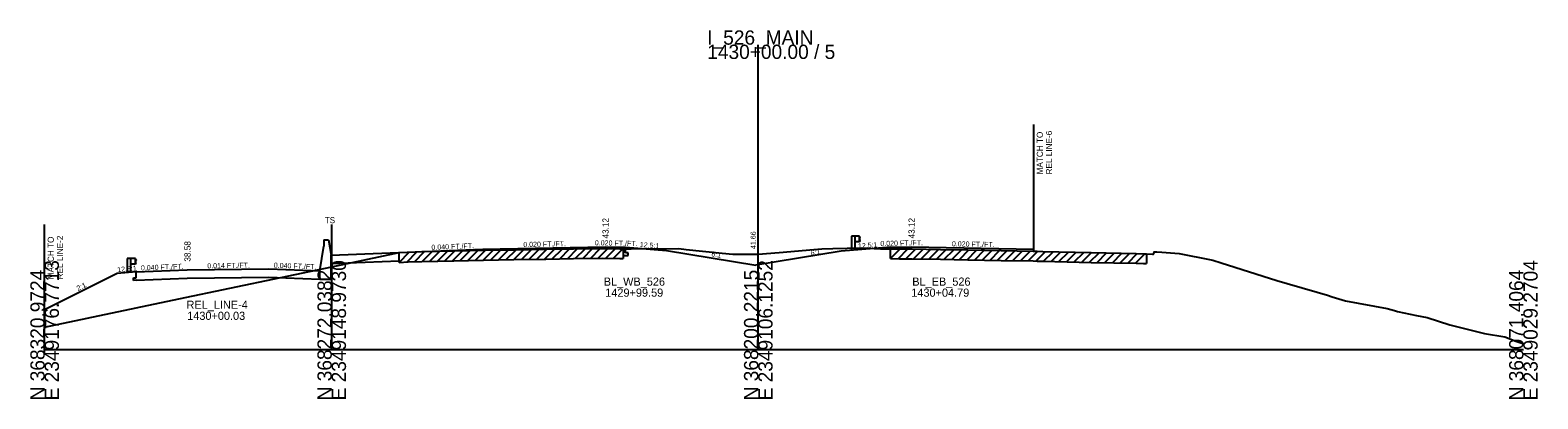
# Model space of a CAD drawing. Extents: x -170 to 2527928, y -10 to 1619750.
# Drawn here: x 3997.2 to 4292.7, y 7490.3 to 7562.6 of the extents above; entities that cross this region are included whole.
import ezdxf

# ---------------------------------------------------------------- set-up
doc = ezdxf.new("R2010")
doc.units = 0
for name, color, linetype in [('RD_GPK_XS_Cell', 7, 'Continuous'), ('RD_PD_NOISE-WALL-GM', 7, 'Continuous'), ('RD_XS_Base', 7, 'Continuous'), ('RD_XS_EarthShd', 7, 'Continuous'), ('RD_XS_ExGround', 7, 'Continuous'), ('RD_XS_ExPaveRet', 7, 'Continuous'), ('RD_XS_GR', 7, 'Continuous'), ('RD_XS_MatchLine', 7, 'Continuous'), ('RD_XS_Pave', 7, 'Continuous'), ('RD_XS_PaveShd', 7, 'Continuous'), ('RD_XS_TieSlope', 7, 'Continuous'), ('RD_XS_TX_Elev_EX', 7, 'Continuous'), ('RD_XS_TX_Slope', 7, 'Continuous'), ('RD_XS_TX_Station', 7, 'Continuous')]:
    doc.layers.add(name, color=color, linetype=linetype)

msp = doc.modelspace()

# ---------------------------------------------------------------- linework, layer by layer
at = {"layer": 'RD_GPK_XS_Cell'}
for p, q in [((4139.91, 7500), (4139.91, 7559.72)), ((4000, 7500), (4056.28, 7500)), ((4056.28, 7500), (4139.91, 7500)), ((4139.91, 7500), (4289.91, 7500))]:
    msp.add_line(p, q, dxfattribs=at)
at = {"layer": 'RD_PD_NOISE-WALL-GM'}
for p, q in [((4053.95, 7515.39), (4054.72, 7520.21)), ((4054.72, 7521.45), (4055.68, 7521.45)), ((4054.72, 7521.45), (4054.72, 7520.21)), ((4055.68, 7521.45), (4056.17, 7518.45)), ((4056.17, 7513.76), (4056.17, 7518.45)), ((4053.95, 7513.76), (4056.17, 7513.76))]:
    msp.add_line(p, q, dxfattribs=at)
at = {"layer": 'RD_XS_Base'}
for p, q in [((4113.91, 7518.91), (4113.91, 7520.04)), ((4165.91, 7519.69), (4165.91, 7520.04)), ((4056.17, 7516.82), (4069.49, 7517.35)), ((4113.41, 7518.42), (4113.91, 7518.41)), ((4114.41, 7518.9), (4113.91, 7518.91)), ((4113.91, 7518.41), (4114.41, 7518.4)), ((4114.41, 7518.4), (4114.41, 7518.9)), ((4193.91, 7519.25), (4193.91, 7519.64)), ((4017.45, 7514.02), (4017.95, 7514.04)), ((4017.45, 7513.52), (4017.45, 7514.02)), ((4017.95, 7514.04), (4017.95, 7515.18)), ((4017.95, 7513.54), (4027.95, 7513.94)), ((4027.95, 7513.94), (4043.95, 7514.16)), ((4043.95, 7514.16), (4053.95, 7513.76)), ((4053.95, 7513.76), (4053.95, 7515.39)), ((4017.95, 7513.54), (4017.45, 7513.52))]:
    msp.add_line(p, q, dxfattribs=at)
at = {"layer": 'RD_XS_EarthShd'}
for p, q in [((4113.91, 7520.04), (4121.91, 7519.4)), ((4165.91, 7520.04), (4156.16, 7519.26)), ((4017.95, 7515.18), (4014.2, 7514.88))]:
    msp.add_line(p, q, dxfattribs=at)
at = {"layer": 'RD_XS_ExGround'}
msp.add_lwpolyline([(4000, 7504.37), (4026.31, 7509.92), (4056.28, 7516.21), (4069.49, 7518.98), (4071.28, 7519.05), (4073.98, 7519.17), (4080.19, 7519.29), (4086.04, 7519.43), (4091.97, 7519.53), (4098.26, 7519.63), (4103.69, 7519.7), (4109.43, 7519.79), (4112.78, 7519.71), (4113.41, 7519.7), (4114.98, 7519.68), (4124.31, 7519.74), (4125.75, 7519.59), (4132.81, 7518.83), (4134.91, 7518.68), (4139.43, 7518.63), (4139.91, 7518.66), (4143.98, 7518.96), (4150.81, 7519.59), (4152.37, 7519.71), (4154.54, 7519.75), (4160.12, 7519.91), (4163.87, 7519.7), (4165.84, 7519.69), (4167.6, 7519.68), (4170.06, 7519.68), (4175.64, 7519.59), (4180.99, 7519.49), (4187.52, 7519.37), (4193.79, 7519.25), (4194.6, 7519.23), (4195.72, 7519.19), (4205.17, 7518.98), (4214.01, 7518.79), (4215.46, 7518.75), (4216.05, 7518.73), (4217.17, 7518.66), (4217.4, 7518.64), (4217.52, 7519.02), (4217.54, 7519.1), (4217.95, 7519.1), (4218.04, 7519.1), (4219.04, 7519.04), (4222.42, 7518.79), (4228.73, 7517.56), (4229.04, 7517.5), (4230.64, 7516.99), (4241.58, 7513.5), (4243.61, 7512.92), (4249.46, 7511.2), (4251.48, 7510.61), (4252.42, 7510.31), (4255.06, 7509.5), (4263.19, 7508), (4264.62, 7507.65), (4265.24, 7507.45), (4268.97, 7506.64), (4271.03, 7506.27), (4275.47, 7504.79), (4282.31, 7503.13), (4286.29, 7502.48), (4288.46, 7501.6), (4289.62, 7501.2), (4289.91, 7501.15)], dxfattribs=at)
at = {"layer": 'RD_XS_ExPaveRet'}
for p, q in [((4105.49, 7517.81), (4107.44, 7519.76)), ((4106.99, 7517.83), (4108.94, 7519.78)), ((4108.49, 7517.86), (4110.4, 7519.76)), ((4069.49, 7517.06), (4071.49, 7519.06)), ((4069.49, 7517.06), (4069.49, 7518.98)), ((4069.49, 7517.06), (4071.28, 7517.13)), ((4070.99, 7517.12), (4072.99, 7519.12)), ((4071.28, 7517.13), (4073.98, 7517.25)), ((4072.49, 7517.18), (4074.48, 7519.18)), ((4073.98, 7517.25), (4080.19, 7517.37)), ((4073.99, 7517.25), (4075.95, 7519.21)), ((4075.49, 7517.28), (4077.45, 7519.24)), ((4076.99, 7517.31), (4078.95, 7519.27)), ((4078.49, 7517.34), (4080.45, 7519.3)), ((4079.99, 7517.37), (4081.95, 7519.33)), ((4080.19, 7517.37), (4086.04, 7517.51)), ((4081.49, 7517.41), (4083.45, 7519.37)), ((4082.99, 7517.44), (4084.95, 7519.41)), ((4084.49, 7517.48), (4086.45, 7519.44)), ((4085.99, 7517.51), (4087.94, 7519.46)), ((4086.04, 7517.51), (4091.97, 7517.61)), ((4087.49, 7517.54), (4089.44, 7519.49)), ((4088.99, 7517.56), (4090.94, 7519.51)), ((4090.49, 7517.59), (4092.44, 7519.54)), ((4091.97, 7517.61), (4098.26, 7517.71)), ((4091.99, 7517.61), (4093.94, 7519.56)), ((4093.49, 7517.64), (4095.44, 7519.58)), ((4094.99, 7517.66), (4096.94, 7519.61)), ((4096.49, 7517.68), (4098.44, 7519.63)), ((4097.99, 7517.71), (4099.93, 7519.65)), ((4098.26, 7517.71), (4103.69, 7517.78)), ((4099.49, 7517.73), (4101.43, 7519.67)), ((4100.99, 7517.74), (4102.93, 7519.69)), ((4102.49, 7517.76), (4104.43, 7519.71)), ((4103.69, 7517.78), (4109.43, 7517.87)), ((4103.99, 7517.78), (4105.94, 7519.73)), ((4109.43, 7517.87), (4112.78, 7517.79)), ((4109.99, 7517.86), (4111.86, 7519.73)), ((4111.49, 7517.82), (4113.37, 7519.7)), ((4112.78, 7517.79), (4113.41, 7517.78)), ((4113.41, 7519.7), (4113.41, 7517.78)), ((4165.84, 7517.78), (4165.84, 7519.69)), ((4165.84, 7517.78), (4167.74, 7519.68)), ((4165.84, 7517.78), (4167.6, 7517.76)), ((4167.34, 7517.76), (4169.25, 7519.68)), ((4167.6, 7517.76), (4170.06, 7517.76)), ((4168.84, 7517.76), (4170.75, 7519.67)), ((4170.06, 7517.76), (4175.64, 7517.67)), ((4170.34, 7517.76), (4172.22, 7519.64)), ((4171.84, 7517.73), (4173.72, 7519.62)), ((4173.34, 7517.71), (4175.22, 7519.59)), ((4174.84, 7517.68), (4176.72, 7519.57)), ((4175.64, 7517.67), (4180.99, 7517.57)), ((4176.34, 7517.66), (4178.22, 7519.54)), ((4177.84, 7517.63), (4179.72, 7519.51)), ((4179.34, 7517.6), (4181.22, 7519.48)), ((4180.84, 7517.57), (4182.72, 7519.46)), ((4180.99, 7517.57), (4187.52, 7517.45)), ((4182.34, 7517.55), (4184.22, 7519.43)), ((4183.84, 7517.52), (4185.72, 7519.4)), ((4185.34, 7517.49), (4187.22, 7519.37)), ((4186.84, 7517.46), (4188.72, 7519.35)), ((4187.52, 7517.45), (4193.79, 7517.34)), ((4188.34, 7517.44), (4190.22, 7519.32)), ((4189.84, 7517.41), (4191.72, 7519.29)), ((4191.34, 7517.38), (4193.22, 7519.26)), ((4192.84, 7517.35), (4194.71, 7519.22)), ((4193.79, 7517.34), (4194.6, 7517.31)), ((4194.34, 7517.32), (4196.2, 7519.18)), ((4194.6, 7517.31), (4195.72, 7517.27)), ((4195.72, 7517.27), (4205.17, 7517.06)), ((4195.84, 7517.27), (4197.71, 7519.14)), ((4197.34, 7517.24), (4199.21, 7519.11)), ((4198.84, 7517.2), (4200.71, 7519.08)), ((4200.34, 7517.17), (4202.21, 7519.05)), ((4201.84, 7517.14), (4203.71, 7519.01)), ((4203.34, 7517.1), (4205.21, 7518.98)), ((4204.84, 7517.07), (4206.71, 7518.95)), ((4205.17, 7517.06), (4214.01, 7516.87)), ((4206.34, 7517.04), (4208.21, 7518.91)), ((4207.84, 7517.01), (4209.71, 7518.88)), ((4209.34, 7516.97), (4211.21, 7518.85)), ((4210.84, 7516.94), (4212.71, 7518.82)), ((4212.34, 7516.91), (4214.21, 7518.78)), ((4213.84, 7516.87), (4215.7, 7518.74)), ((4214.01, 7516.87), (4215.46, 7516.83)), ((4215.46, 7516.83), (4216.05, 7516.81)), ((4216.05, 7518.73), (4216.05, 7516.81))]:
    msp.add_line(p, q, dxfattribs=at)
at = {"layer": 'RD_XS_GR'}
for p, q in [((4158.82, 7522.22), (4158.16, 7522.22)), ((4158.16, 7522.22), (4158.16, 7519.42)), ((4159.74, 7522.22), (4158.82, 7522.22)), ((4158.82, 7522.22), (4158.82, 7519.48)), ((4159.74, 7521.05), (4158.82, 7521.05)), ((4159.74, 7521.05), (4159.74, 7522.22)), ((4159.74, 7522.15), (4159.91, 7521.95)), ((4159.91, 7521.9), (4159.74, 7521.7)), ((4159.91, 7521.38), (4159.74, 7521.58)), ((4159.74, 7521.13), (4159.91, 7521.33)), ((4159.91, 7521.95), (4159.91, 7521.9)), ((4159.91, 7521.33), (4159.91, 7521.38)), ((4016.86, 7517.83), (4016.2, 7517.83)), ((4016.2, 7517.83), (4016.2, 7515.04)), ((4017.78, 7517.83), (4016.86, 7517.83)), ((4016.86, 7517.83), (4016.86, 7515.09)), ((4017.78, 7516.67), (4017.78, 7517.83)), ((4017.78, 7517.76), (4017.95, 7517.56)), ((4017.95, 7517.51), (4017.78, 7517.31)), ((4017.95, 7516.99), (4017.78, 7517.19)), ((4017.78, 7516.74), (4017.95, 7516.94)), ((4017.95, 7517.56), (4017.95, 7517.51)), ((4017.95, 7516.94), (4017.95, 7516.99)), ((4017.78, 7516.67), (4016.86, 7516.67))]:
    msp.add_line(p, q, dxfattribs=at)
at = {"layer": 'RD_XS_MatchLine'}
for p, q in [((4193.91, 7519.64), (4193.91, 7544.06)), ((4000, 7499.09), (4000, 7524.46)), ((4056.28, 7500), (4056.28, 7524.46))]:
    msp.add_line(p, q, dxfattribs=at)
at = {"layer": 'RD_XS_Pave'}
for p, q in [((4085.91, 7519.64), (4109.91, 7520.12)), ((4169.91, 7520.12), (4193.91, 7519.64)), ((4027.95, 7515.58), (4043.95, 7515.79))]:
    msp.add_line(p, q, dxfattribs=at)
at = {"layer": 'RD_XS_PaveShd'}
for p, q in [((4109.91, 7520.12), (4113.91, 7520.04)), ((4165.91, 7520.04), (4169.91, 7520.12)), ((4056.17, 7518.45), (4085.91, 7519.64)), ((4017.95, 7515.18), (4027.95, 7515.58)), ((4043.95, 7515.79), (4053.95, 7515.39))]:
    msp.add_line(p, q, dxfattribs=at)
at = {"layer": 'RD_XS_TieSlope'}
for p, q in [((4121.91, 7519.4), (4139.45, 7516.48)), ((4156.16, 7519.26), (4139.45, 7516.48)), ((4014.2, 7514.88), (4000, 7507.78)), ((4000, 7507.78), (4000, 7504.37))]:
    msp.add_line(p, q, dxfattribs=at)

# ---------------------------------------------------------------- texts
at = {"layer": 'RD_GPK_XS_Cell'}
for s, p in [('I_526_MAIN', (4129.91, 7559.72)), ('1430+00.00 / 5', (4129.91, 7556.92))]:
    msp.add_text(s, height=2.8, dxfattribs=at).set_placement(p)
for s, p in [('E 2349176.7713', (4002.8, 7490)), ('E 2349148.9730', (4059.08, 7490)), ('E 2349106.1252', (4142.71, 7490)), ('E 2349029.2704', (4292.71, 7490)), ('N 368320.9724', (4000, 7490)), ('N 368272.0382', (4056.28, 7490)), ('N 368200.2215', (4139.91, 7490)), ('N 368071.4064', (4289.91, 7490))]:
    msp.add_text(s, height=2.8, rotation=90, dxfattribs=at).set_placement(p)
at = {"layer": 'RD_XS_MatchLine'}
msp.add_text('TS', height=1.2, dxfattribs=at).set_placement((4054.91, 7524.73))
at = {"layer": 'RD_XS_TX_Elev_EX'}
msp.add_text('41.66', height=1, rotation=90, dxfattribs=at).set_placement((4139.41, 7519.66))
at = {"layer": 'RD_XS_TX_Slope'}
for s, rotation, p in [('0.040 FT./FT.', 2.2906, (4075.85, 7519.49)), ('0.020 FT./FT.', 1.1458, (4093.85, 7520.05)), ('0.020 FT./FT.', 358.8542, (4107.86, 7520.41)), ('12.5:1', 355.4261, (4116.66, 7520.08)), ('12.5:1', 4.5739, (4159.49, 7519.74)), ('0.020 FT./FT.', 1.1458, (4163.85, 7520.25)), ('0.020 FT./FT.', 358.8542, (4177.86, 7520.21)), ('0.014 FT./FT.', 0.7806, (4031.89, 7515.88)), ('0.040 FT./FT.', 357.7094, (4044.91, 7516.01)), ('6:1', 350.5377, (4130.66, 7518.26)), ('6:1', 9.4623, (4150.24, 7518.41)), ('12.5:1', 4.5739, (4014.27, 7515.13)), ('0.040 FT./FT.', 2.2906, (4018.89, 7515.46)), ('2:1', 26.5651, (4006.55, 7511.43))]:
    msp.add_text(s, height=1, rotation=rotation, dxfattribs=at).set_placement(p)
at = {"layer": 'RD_XS_TX_Station'}
for s, p in [('MATCH TO', (4195.71, 7534.29)), ('REL LINE-6', (4197.51, 7534.29)), (' 43.12', (4110.56, 7521.29)), (' 43.12', (4170.56, 7521.3)), ('MATCH TO', (4001.8, 7513.73)), ('REL LINE-2', (4003.6, 7513.73)), (' 38.58', (4028.6, 7516.75))]:
    msp.add_text(s, height=1.2, rotation=90, dxfattribs=at).set_placement(p)
for s, p in [('BL_WB_526', (4109.61, 7512.48)), ('BL_EB_526', (4170.1, 7512.48)), ('1429+99.59', (4109.91, 7510.32)), ('1430+04.79', (4169.91, 7510.32)), ('REL_LINE-4', (4027.82, 7507.95)), ('1430+00.03', (4027.95, 7505.78))]:
    msp.add_text(s, height=1.6, dxfattribs=at).set_placement(p)

doc.saveas('drawing.dxf')
